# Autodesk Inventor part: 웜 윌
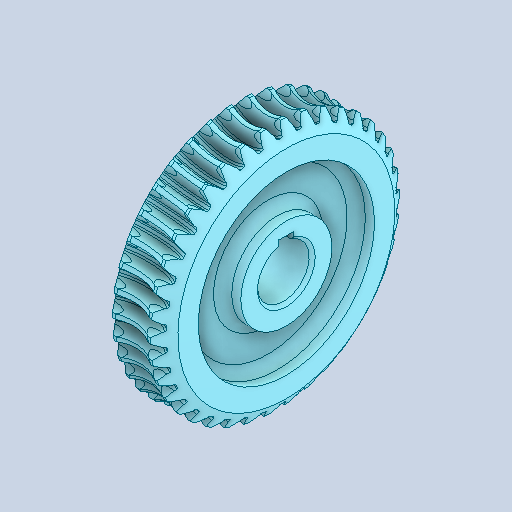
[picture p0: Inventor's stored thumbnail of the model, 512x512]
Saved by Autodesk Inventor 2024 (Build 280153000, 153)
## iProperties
Created: 2026-01
Part Number: 웜 윌
Material: 강철, 합금
Document SubType Name: Modeling
Designer: 2-10
Density: 7.73 g/cm^3
Appearance: 기본값
Sending System: Autodesk Inventor 2026
Preprocessor: ST-DEVELOPER v20.1
Author: jhkim
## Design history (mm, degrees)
node "웜 휠1"
node "솔리드2"
node "솔리드1"
